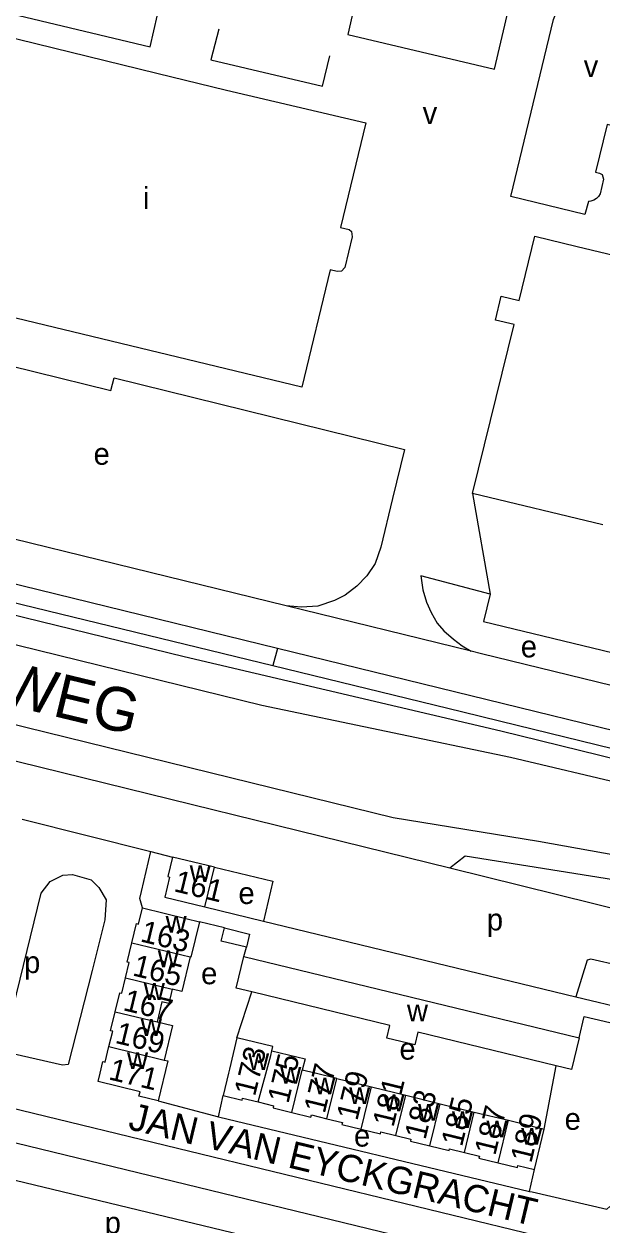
# Model space of a CAD drawing. Extents: x 162804 to 165059, y 381530 to 382901.
# Drawn here: x 163660.6 to 163766.6, y 382222.2 to 382442.3 of the extents above; entities that cross this region are included whole.
import ezdxf

# ---------------------------------------------------------------- set-up
doc = ezdxf.new("R2010")
doc.units = 0
for name, color, linetype in [('BLT_Basislijn', 7, 'Continuous'), ('BLT_Bebouwing', 7, 'Continuous'), ('BLT_Centroide', 7, 'Continuous'), ('BLT_Huisnummer', 7, 'Continuous'), ('BLT_Huisnummer_ tussenligend', 7, 'Continuous'), ('BLT_Onderverdeling_panden', 7, 'Continuous'), ('BLT_Straatnaam', 7, 'Continuous'), ('BLT_Straatnaam_hoofdweg', 7, 'Continuous'), ('BLT_Vlakafsluiter', 7, 'Continuous')]:
    doc.layers.add(name, color=color, linetype=linetype)

msp = doc.modelspace()

# ---------------------------------------------------------------- linework, layer by layer
at = {"layer": 'BLT_Basislijn'}
for p, q in [((163763.49, 382407.39), (163749.9, 382410.7)), ((163581.91, 382355.04), (163706.23, 382324.72)), ((163584.87, 382346.69), (163704.22, 382317.48)), ((163738.67, 382287.56), (163577.51, 382327.26)), ((163706.23, 382324.72), (163740.86, 382316.28)), ((163704.22, 382317.48), (163749.83, 382307.92)), ((163740.86, 382316.28), (163748.08, 382314.51)), ((163748.08, 382314.51), (163865.52, 382285.74)), ((163749.83, 382307.92), (163867.3, 382280.32)), ((163660.23, 382296.57), (163683.84, 382290.63)), ((163682.14, 382283.3), (163683.84, 382290.63)), ((163683.84, 382290.63), (163687.83, 382289.62)), ((163805.07, 382271.2), (163738.67, 382287.56)), ((163693.77, 382280.48), (163704.54, 382277.88)), ((163704.54, 382277.88), (163761.83, 382264)), ((163700.94, 382271.41), (163701.37, 382273.09)), ((163699.63, 382256.48), (163702.36, 382264.93)), ((163761.83, 382264), (163773.45, 382261.18)), ((163756.01, 382239.77), (163758.22, 382251.35)), ((163685.19, 382244.93), (163696.28, 382241.99)), ((163696.28, 382241.99), (163697.1, 382245.89)), ((163696.28, 382241.99), (163753.29, 382228.35)), ((163753.29, 382228.35), (163754.21, 382232.37))]:
    msp.add_line(p, q, dxfattribs=at)
for points in [[(163749.9, 382410.7), (163757.71, 382443.14), (163759.36, 382447.39), (163761.87, 382450.75), (163765.26, 382453.54), (163769.01, 382455.65), (163772.66, 382456.98), (163775.81, 382457.75), (163777.48, 382457.32), (163769.44, 382424.32), (163768.98, 382423.79), (163768.29, 382423.72), (163767.55, 382423.9), (163765.42, 382415.15), (163766.16, 382414.97), (163766.65, 382414.72), (163766.91, 382413.92), (163766.29, 382411.21), (163765.94, 382410.73), (163765.58, 382410.35), (163765.13, 382410.03), (163764.59, 382409.85), (163764.12, 382409.81), (163763.49, 382407.39)], [(163654.21, 382445.19), (163683.7, 382438.16), (163685.08, 382444.03)], [(163696.31, 382441.36), (163694.87, 382435.74), (163715.37, 382430.92), (163716.69, 382436.52)], [(163634.83, 382385.42), (163676.54, 382375.15)], [(163676.54, 382375.15), (163677.1, 382377.45)], [(163677.1, 382377.45), (163730.39, 382364.34)], [(163730.39, 382364.34), (163728.21, 382355.38), (163726.03, 382346.43), (163724.98, 382343.43), (163723.48, 382341.18), (163721.65, 382339.28), (163719.47, 382337.63), (163717.56, 382336.64), (163714.48, 382335.64), (163711.49, 382335.41), (163708.67, 382335.7)], [(163707.11, 382327.85), (163603.75, 382353.17), (163564.64, 382362.74)], [(163560.74, 382358), (163689.95, 382326.42), (163748.05, 382312.74), (163777.15, 382305.63), (163865.05, 382284.21)], [(163708.67, 382335.7), (163624.27, 382356.35)], [(163746.11, 382337.83), (163733.39, 382341.15), (163733.77, 382338.63), (163734.44, 382336.35), (163735.29, 382334.45), (163736.39, 382332.5), (163737.57, 382331.08), (163739.38, 382329.56), (163740.95, 382328.37), (163742.63, 382327.36)], [(163746.11, 382337.83), (163744.87, 382332.83), (163867.1, 382303.32)], [(163809.11, 382282.79), (163754.98, 382292.49), (163728.32, 382296.8), (163574.82, 382334.53)], [(164126.41, 382226.62), (163965.37, 382264.86), (163810.46, 382302.53), (163707.11, 382327.85)], [(163859.14, 382298.92), (163744.49, 382326.9), (163742.63, 382327.36)], [(163800.49, 382280.36), (163741.52, 382289.8), (163738.67, 382287.56)], [(163673.08, 382268.86), (163668.66, 382251.62), (163667.67, 382251.48), (163656.64, 382253.98), (163663.76, 382283.01), (163665.36, 382285.14), (163667.68, 382286.3), (163669.49, 382286.41), (163672.93, 382285.46), (163674.3, 382284.04), (163675.64, 382281.8), (163675.43, 382278.13), (163673.08, 382268.86)], [(163695.53, 382287.77), (163706.26, 382285.21), (163704.54, 382277.88)], [(163682.31, 382280.29), (163681.85, 382282.05), (163682.14, 382283.3)], [(163697.36, 382276.63), (163692.76, 382277.77)], [(163535.81, 382273.16), (163541.5, 382271.99), (163758.91, 382219.21), (163759.07, 382218.46), (163758.45, 382214.75), (163754.63, 382199.3), (163754.03, 382197.92), (163752.81, 382197.95), (163531.23, 382251.04)], [(163775.18, 382268.46), (163764.55, 382270.92), (163763.9, 382270.71), (163761.83, 382264)], [(163534.57, 382267.49), (163748.1, 382215.63), (163753.62, 382214.11), (163753.7, 382213.43), (163752.3, 382208.06), (163750.49, 382208.3), (163532.9, 382260.7)], [(163762.41, 382256.49), (163763.33, 382260.41), (163774.57, 382257.76)], [(163753.29, 382228.35), (163753.78, 382228.24), (163767.47, 382225.07), (163768.05, 382225.57)]]:
    msp.add_lwpolyline(points, dxfattribs=at)
at = {"layer": 'BLT_Bebouwing'}
for p, q in [((163762.07, 382401.56), (163778.21, 382397.64)), ((163766.75, 382350.51), (163742.83, 382356.28)), ((163695.53, 382287.77), (163687.83, 382289.62)), ((163693.77, 382280.48), (163695.53, 382287.77)), ((163686.4, 382282.26), (163693.77, 382280.48)), ((163699.53, 382265.62), (163700.94, 382271.41)), ((163700.94, 382271.41), (163762.41, 382256.49)), ((163702.36, 382264.93), (163699.53, 382265.62)), ((163727.71, 382258.75), (163702.36, 382264.93)), ((163727.15, 382256.45), (163727.71, 382258.75)), ((163732.25, 382255.21), (163727.15, 382256.45)), ((163732.81, 382257.54), (163732.25, 382255.21)), ((163758.22, 382251.35), (163732.81, 382257.54)), ((163762.41, 382256.49), (163760.99, 382250.67)), ((163760.99, 382250.67), (163758.22, 382251.35)), ((163717.94, 382249.04), (163724.31, 382247.49)), ((163724.31, 382247.49), (163730.6, 382245.96)), ((163730.6, 382245.96), (163736.9, 382244.42)), ((163736.9, 382244.42), (163743.18, 382242.89)), ((163743.18, 382242.89), (163749.45, 382241.37)), ((163749.45, 382241.37), (163756.01, 382239.77))]:
    msp.add_line(p, q, dxfattribs=at)
for points in [[(163746.89, 382434.06), (163753.46, 382461.95)], [(163721.11, 382445.25), (163719.97, 382440.41), (163746.89, 382434.06)], [(163653.23, 382441.11), (163684.98, 382433.33), (163697.71, 382430.22), (163723.26, 382424.22), (163718.64, 382405.04)], [(163718.64, 382405.04), (163720.25, 382404.66), (163720.65, 382404.28), (163720.81, 382403.29), (163719.45, 382397.69), (163718.83, 382397.04), (163718.05, 382396.96), (163716.77, 382397.27), (163711.58, 382375.77), (163641.54, 382392.64), (163641.87, 382394.02)], [(163742.83, 382356.28), (163750.48, 382387.23), (163747.05, 382388.07), (163748.12, 382392.46), (163751.44, 382391.66), (163754.31, 382403.45), (163762.07, 382401.56)], [(163687.83, 382289.62), (163686.97, 382286.04), (163687.29, 382285.96), (163686.4, 382282.26)], [(163680.39, 382273.9), (163681.24, 382277.42), (163681.59, 382277.34), (163682.31, 382280.29)], [(163682.31, 382280.29), (163690.29, 382278.36), (163692.76, 382277.77)], [(163692.76, 382277.77), (163691.2, 382271.28), (163691.06, 382271.32)], [(163701.37, 382273.09), (163696.75, 382274.23), (163697.36, 382276.63)], [(163697.36, 382276.63), (163701.97, 382275.49), (163701.37, 382273.09)], [(163679.2, 382267.49), (163679.88, 382270.3), (163679.54, 382270.38), (163680.39, 382273.9)], [(163691.06, 382271.32), (163689.51, 382264.99), (163687.77, 382265.42)], [(163677.3, 382261.28), (163678.14, 382264.76), (163678.52, 382264.67), (163679.2, 382267.49)], [(163687.77, 382265.42), (163687.14, 382262.81), (163685.88, 382263.11), (163684.99, 382259.42)], [(163676.17, 382254.87), (163676.86, 382257.69), (163676.46, 382257.79), (163677.3, 382261.28)], [(163684.99, 382259.42), (163687.8, 382258.73), (163686.28, 382252.42)], [(163699.63, 382256.48), (163698.27, 382250.72), (163698.1, 382250), (163697.1, 382245.89)], [(163706.07, 382254.11), (163706.26, 382254.9), (163699.63, 382256.48)], [(163685.19, 382244.93), (163681.68, 382245.77), (163681.89, 382246.61), (163674.19, 382248.47), (163674.56, 382250), (163675.07, 382252.14), (163675.49, 382252.04), (163676.17, 382254.87)], [(163706.07, 382254.11), (163712.14, 382252.61), (163711.63, 382250.58)], [(163686.28, 382252.42), (163686.97, 382252.25), (163685.19, 382244.93)], [(163717.94, 382249.04), (163713.99, 382250), (163711.63, 382250.58)], [(163697.1, 382245.89), (163700.58, 382245.05), (163700.67, 382245.42), (163703.51, 382244.73)], [(163703.51, 382244.73), (163706.36, 382244.03), (163706.27, 382243.66), (163709.74, 382242.81)], [(163709.74, 382242.81), (163713.22, 382241.96), (163713.32, 382242.36), (163716.15, 382241.67)], [(163716.15, 382241.67), (163718.98, 382240.98), (163718.89, 382240.59), (163722.42, 382239.73)], [(163722.42, 382239.73), (163725.96, 382238.87), (163726.05, 382239.24), (163728.8, 382238.57)], [(163728.8, 382238.57), (163731.55, 382237.9), (163731.47, 382237.54), (163735.02, 382236.68)], [(163754.21, 382232.37), (163755.27, 382236.72), (163756.01, 382239.77)], [(163735.02, 382236.68), (163738.57, 382235.81), (163738.64, 382236.13), (163741.38, 382235.47)], [(163741.38, 382235.47), (163744.11, 382234.8), (163744.03, 382234.46), (163747.56, 382233.6)], [(163747.56, 382233.6), (163751.08, 382232.74), (163751.17, 382233.11), (163754.21, 382232.37)]]:
    msp.add_lwpolyline(points, dxfattribs=at)
at = {"layer": 'BLT_Onderverdeling_panden'}
for p, q in [((163680.39, 382273.9), (163691.06, 382271.32)), ((163679.2, 382267.49), (163687.77, 382265.42)), ((163677.3, 382261.28), (163684.99, 382259.42)), ((163676.17, 382254.87), (163686.28, 382252.42)), ((163709.74, 382242.81), (163711.63, 382250.58)), ((163716.15, 382241.67), (163717.94, 382249.04)), ((163722.42, 382239.73), (163724.31, 382247.49)), ((163728.8, 382238.57), (163730.6, 382245.96)), ((163735.02, 382236.68), (163736.9, 382244.42)), ((163741.38, 382235.47), (163743.18, 382242.89)), ((163747.56, 382233.6), (163749.45, 382241.37))]:
    msp.add_line(p, q, dxfattribs=at)
msp.add_lwpolyline([(163703.51, 382244.73), (163705.86, 382253.22), (163706.07, 382254.11)], dxfattribs=at)
at = {"layer": 'BLT_Vlakafsluiter'}
for p, q in [((163742.83, 382356.28), (163746.11, 382337.83)), ((163742.63, 382327.36), (163708.67, 382335.7)), ((163707.11, 382327.85), (163706.23, 382324.72))]:
    msp.add_line(p, q, dxfattribs=at)

# ---------------------------------------------------------------- texts
at = {"layer": 'BLT_Centroide'}
for s, p in [('v', (163763.25, 382432.61)), ('v', (163733.71, 382424.03)), ('i', (163682.4, 382408.44)), ('e', (163673.35, 382361.54)), ('e', (163751.71, 382326.23)), ('w', (163690.97, 382285.06)), ('e', (163699.92, 382281.02)), ('w', (163686.56, 382275.78)), ('p', (163745.49, 382276.18)), ('p', (163660.6, 382268.36)), ('w', (163685.13, 382269.44)), ('e', (163693.08, 382266.31)), ('w', (163682.56, 382263.44)), ('w', (163730.83, 382259.52)), ('w', (163682, 382256.84)), ('e', (163729.46, 382252.49)), ('w', (163679.48, 382250.75)), ('w', (163701.69, 382250.59)), ('w', (163707.58, 382248.08)), ('w', (163713.84, 382246.12)), ('w', (163720.23, 382244.36)), ('w', (163726.52, 382243.03)), ('w', (163732.86, 382241.31)), ('w', (163739.09, 382239.95)), ('e', (163759.75, 382239.63)), ('w', (163745.41, 382238.23)), ('e', (163721.12, 382236.55)), ('w', (163751.78, 382236.89)), ('p', (163675.39, 382220.6))]:
    msp.add_text(s, height=4, dxfattribs=at).set_placement(p)
at = {"layer": 'BLT_Huisnummer'}
for s, rotation, p in [('161', 346.4435, (163687.9, 382283.39)), ('163', 346.4435, (163681.76, 382274.19)), ('167', 346.4413, (163678.59, 382261.58)), ('173', 76.3219, (163702.95, 382245.63)), ('171', 346.4691, (163675.93, 382248.91)), ('177', 76.3257, (163715.74, 382242.48)), ('181', 76.3211, (163728.34, 382239.97)), ('185', 76.3251, (163740.92, 382236.39)), ('189', 76.3139, (163753.63, 382233.39))]:
    msp.add_text(s, height=4, rotation=rotation, dxfattribs=at).set_placement(p)
at = {"layer": 'BLT_Huisnummer_ tussenligend'}
for s, rotation, p in [('165', 346.4413, (163680.33, 382267.95)), ('169', 346.4413, (163677.13, 382255.59)), ('175', 76.3219, (163709.06, 382244.3)), ('179', 76.3257, (163721.72, 382241.16)), ('183', 76.3211, (163734.21, 382237.67)), ('187', 76.3251, (163747.02, 382234.78))]:
    msp.add_text(s, height=4, rotation=rotation, dxfattribs=at).set_placement(p)
at = {"layer": 'BLT_Straatnaam'}
msp.add_text('JAN VAN EYCKGRACHT', height=4.9999, rotation=346.5464, dxfattribs=at).set_placement((163679.51, 382239.78))
at = {"layer": 'BLT_Straatnaam_hoofdweg'}
msp.add_text('GELDROPSEWEG', height=8, rotation=346.4691, dxfattribs=at).set_placement((163591.05, 382333.5))

doc.saveas('drawing.dxf')
